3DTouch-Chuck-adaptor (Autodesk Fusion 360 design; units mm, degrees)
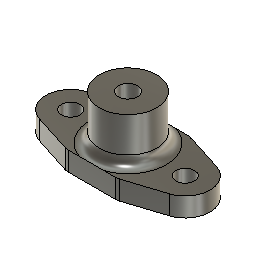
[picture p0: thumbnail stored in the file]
sketch "Sketch1" plane through (0, 0, 0) normal (0, 0, 1) x axis (1, 0, 0)
  line L1 (-12.9, -5.7) -> (12.9, -5.7)
  line L2 (-12.9, 5.7) -> (-12.9, -5.7)
  line L3 (12.9, 5.7) -> (-12.9, 5.7)
  line L4 (12.9, -5.7) -> (12.9, 5.7)
  line L5 (-12.9, 5.7) -> (12.9, -5.7)
  line L6 (12.9, 5.7) -> (-12.9, -5.7)
  line L7 (9, 0) -> (0, 0)
  line L8 (4, 5.7) -> (0, 5.7)
  line L9 (-4, 5.7) -> (0, 5.7)
  line L10 (-10.1914, 3.7136) -> (-4, 5.7)
  line L11 (10.1914, 3.7136) -> (4, 5.7)
  line L12 (10.1914, -3.7136) -> (4, -5.7)
  line L13 (4, -5.7) -> (0, -5.7)
  line L14 (-4, -5.7) -> (0, -5.7)
  line L15 (-10.1914, -3.7136) -> (-4, -5.7)
  circle C1 centre (9, 0) radius 1.45
  circle C2 centre (-9, 0) radius 1.45
  circle C3 centre (9, 0) radius 3.9
  circle C4 centre (-9, 0) radius 3.9
  circle C5 centre (0, 0) radius 1.5
  circle C6 centre (0, 0) radius 4.5
  point P6 (0, 0)
  point P1 (0, 0)
  point P7 (0, 0)
  point P8 (9, 0)
  point P9 (9, 0)
  point P13 (0, 5.7)
  point P16 (-10.1914, 3.7136)
  point P17 (10.1914, 3.7136)
  point P20 (0, -5.7)
  point P14 (4, 5.7)
  point P18 (4, -5.7)
  point P15 (-4, 5.7)
  point P21 (-4, -5.7)
  point P22 (-10.1914, -3.7136)
  point P19 (10.1914, -3.7136)
  point P23 (0, 0)
  point P4 (-12.9, 5.7)
  point P5 (12.9, 5.7)
  point P3 (-12.9, -5.7)
  horizontal L1
  perpendicular L1 L2
  parallel L1 L3
  parallel L2 L4
  coincident L5 P6
  coincident L6 P6
  coincident P1 P6
  coincident P1 P7
  horizontal L7
  coincident P8 P9
  concentric C1 C3
  tangent L4 C3
  concentric C2 C4
  tangent L2 C4
  midpoint L3 P13
  parallel L3 L8
  parallel L3 L9
  coincident C4 P16
  tangent C4 L10
  coincident C3 P17
  tangent C3 L11
  symmetric L7 P13 P20
  symmetric L7 P14 P18
  symmetric L7 P15 P21
  symmetric L7 P16 P22
  symmetric L7 P17 P19
  coincident P1 P23
  dimension "d1" distance P4 P5 = 25.8
  dimension "d2" distance P3 P4 = 11.4
  dimension "d3" distance P7 P8 = 9
  dimension "d4" diameter C1 = 2.9
  dimension "d5" diameter C2 = 2.9
  dimension "d6" distance P13 P14 = 4
  dimension "d7" distance P13 P15 = 4
  dimension "d8" diameter C5 = 3
  dimension "d9" distance C5 = 3
extrude "Extrude1" new body sketch "Sketch1" profile of C5 C6 along normal blind 10
extrude "Extrude2" add sketch "Sketch1" profile of L1 L3 C1 C2 C3 C4 L8 L9 L10 L11 L12 L13 L14 L15 C6 along normal blind 3
fillet "Fillet1" radius 2
fillet "Fillet2" radius 1.5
